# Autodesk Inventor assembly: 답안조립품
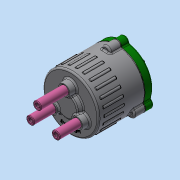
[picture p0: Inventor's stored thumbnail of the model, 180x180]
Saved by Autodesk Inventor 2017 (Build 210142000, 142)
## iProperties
Part Number: 답안조립품
Material: 일반
Document SubType Name: Assembly
Designer: MRC
Author: MRC
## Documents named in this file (15)
- C:\Users\MRC\Desktop\620811V1009\답안조립품.iam
- C:\Users\MRC\Desktop\620811V1009\본체.ipt
- C:\Users\MRC\Desktop\620811V1009\개스킷.ipt
- C:\Users\MRC\Desktop\620811V1009\커버.ipt
- C:\Users\MRC\Desktop\620811V1009\베어링 NA 4900.ipt
- C:\Users\MRC\Desktop\620811V1009\오일 실.ipt
- C:\Users\MRC\Desktop\620811V1009\메인 축.ipt
- C:\Users\MRC\Desktop\620811V1009\멈춤링 22x1.2.ipt
- C:\Users\MRC\Desktop\620811V1009\판캠.ipt
- C:\Users\MRC\Desktop\620811V1009\멈춤링 10x1.ipt
- C:\Users\MRC\Desktop\620811V1009\볼트 M5.ipt
- C:\Users\MRC\Desktop\620811V1009\슬라이드 축.ipt
- C:\Users\MRC\Desktop\620811V1009\가변스프링1.ipt
- C:\Users\MRC\Desktop\620811V1009\가변스프링2.ipt
- C:\Users\MRC\Desktop\620811V1009\가변스프링3.ipt
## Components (4 placed, 4 different names)
1. 개스킷:1
2. 가변스프링1:1
3. 가변스프링2:1
4. 가변스프링3:1
